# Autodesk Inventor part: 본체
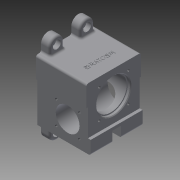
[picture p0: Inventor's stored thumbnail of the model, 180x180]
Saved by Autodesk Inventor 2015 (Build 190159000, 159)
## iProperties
Created: 2024-11
Part Number: 본체
Material: 일반
Document SubType Name: Modeling
Designer: 102-5
Density: 1 g/cm^3
Appearance: 기본값
Author: 102-5
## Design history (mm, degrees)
sketch "스케치1"
  geometry: L1 (-38, 33)-(38, 33); L2 (38, 33)-(38, -52); L3 (38, -52)-(-38, -52); L4 (-38, -52)-(-38, 33); 2 further points
  constraints: 8 end point, 2 parallel, 1 horizontal, 1 midpoint, 1 perpendicular, 1 vertical alignment
  dimensions: "d0" = 76 distance between parallel lines of L2 L4; "d1" = 85 distance between parallel lines of L3 L1; "d2" = 33 distance from line of point (0, 0) L1
extrude "돌출1" new body sketch "스케치1" distance "d3" = 74; taper "d4" = 0 deg
sketch "스케치2"
  geometry: L1 (-33, -38)-(52, -38) reference; L2 (52, -38)-(52, 38) reference; L3 (-4, -38)-(52, -38); L4 (52, -38)-(52, -36); L5 (52, -36)-(-4, -36); L6 (-4, -36)-(-4, -38); 1 further point
  constraints: 8 end point, 2 parallel, 2 point on line, 1 horizontal, 1 perpendicular
  dimensions: "d5" = 2 distance between parallel lines of L5 L1; "d6" = 56 distance between parallel lines of L2 L6
extrude "돌출2" cut sketch "스케치2" stored distance "d7" = 74; taper "d8" = 0 deg
sketch "스케치4"
  geometry: L1 (0, -52)-(-74, -52) reference; L2 (-74, -52)-(-74, 33) reference; L3 (-74, 33)-(0, 33) reference; L4 (0, 33)-(0, -52) reference; L5 (0, 33)-(-74, 33) reference; L6 (-74, -52)-(-74, 4) reference; L7 (-70, 33)-(-74, 33); L8 (-74, 33)-(-74, -33); L9 (-74, -33)-(-70, -33); L10 (-70, -33)-(-70, 33); 1 further point
  constraints: 8 end point, 2 parallel, 2 point on line, 1 horizontal, 1 perpendicular
  dimensions: "d9" = 4 distance between parallel lines of L2 L10; "d10" = 66 distance between parallel lines of L9 L3
extrude "돌출3" cut sketch "스케치4" stored distance "d11" = 4 (= d9); taper "d12" = 0 deg
sketch "스케치5"
  geometry: L1 (33, -38)-(33, 38) reference; L2 (53, 21)-(-72, 21); L3 (43, 31)-(-62, 31); L4 (-62, 11)-(43, 11); A1 r 10 centre (43, 21) between (43, 11) and (43, 31); A2 r 10 centre (-62, 21) between (-62, 31) and (-62, 11); 2 further points
  constraints: 8 end point, 6 point on circle, 4 tangent, 2 centre point, 2 point on line, 1 horizontal, 1 midpoint, 1 parallel
  dimensions: "d15" = 10 radius of A1; "d16" = 21 vertical distance of point (0, 0) A1.centre; "d17" = 105 distance of A2.centre A1.centre; "d18" = 10 distance from line of L1 A1.centre
extrude "돌출4" join sketch "스케치5" distance "d19" = 12; taper "d20" = 0 deg
sketch "스케치6"
  geometry: A1 r 10 centre (-43, 21) between (-43, 31) and (-43, 11) reference; 1 further point
hole "구멍1" sketch "스케치6" at (-43, 21) diameter "d21" = 6.6; stored, may be unused: countersink angle "d25" = 90 deg, drill point angle "d27" = 118 deg; dims "d22" = 6, "d23" = 11, "d24" = 6.6, "d26" = 8
sketch "스케치7"
  geometry: A1 r 10 centre (62, 21) between (62, 11) and (62, 31) reference; 1 further point
hole "구멍2" sketch "스케치7" at (62, 21) diameter "d28" = 6.6; stored, may be unused: countersink angle "d32" = 90 deg, drill point angle "d34" = 118 deg; dims "d29" = 6, "d30" = 11, "d31" = 6.6, "d33" = 8
sketch "스케치8"
  geometry: L1 (0, 0)-(0, 56) reference; L2 (0, 85)-(70, 85) reference; C1 r 16.5 at (42, 28); 1 further point
  constraints: 1 centre point
  dimensions: "d35" = 33 diameter of C1; "d36" = 42 distance from line of C1.centre L1; "d37" = 57 distance from line of C1.centre L2
extrude "돌출5" cut sketch "스케치8" stored distance "d38" = 12; taper "d39" = 0 deg
sketch "스케치9"
  geometry: L1 (42, 28)-(58.5, 28); L2 (42, 28)-(58, 44); 2 further points
  constraints: 4 end point, 1 coincident, 1 horizontal, 1 horizontal alignment, 1 other
  dimensions: "d40" = 45 deg angle of L2 L1; "d42" = 16 horizontal distance of point (58, 44) L1.start
hole "구멍3" sketch "스케치9" at (58, 44) diameter "d43" = 3.242; stored, may be unused: countersink angle "d47" = 90 deg, drill point angle "d49" = 118 deg; dims "d44" = 8, "d45" = 11, "d46" = 6.6, "d48" = 10
sketch "스케치10"
  geometry: L1 (52, -36)-(52, 36) reference; L2 (69.046, -6)-(37, -6); L3 (37, -6)-(37, 6); L4 (37, 6)-(69.046, 6); L5 (69.046, 6)-(69.046, -6); 2 further points
  constraints: 8 end point, 2 parallel, 1 horizontal, 1 horizontal alignment, 1 midpoint, 1 perpendicular
  dimensions: "d53" = 12 distance between parallel lines of L4 L2; "d54" = 15 distance between parallel lines of L1 L3; "d55" = 32.04603 distance between parallel lines of L5 L3
extrude "돌출6" cut sketch "스케치10" stored distance "d56" = 12; taper "d57" = 0 deg
sketch "스케치11"
  geometry: C1 r 23.5 at (33, 38); 1 further point
  constraints: 1 centre point, 1 coincident
  dimensions: "d58" = 47 diameter of C1
extrude "돌출7" cut sketch "스케치11" distance "d59" = 4; taper "d60" = 0 deg
sketch "스케치12"
  geometry: C1 r 23.5 at (0, 0) reference; C2 r 22 at (0, 0)
  constraints: 1 centre point, 1 coincident
  dimensions: "d61" = 44 diameter of C2
extrude "돌출8" cut sketch "스케치12" distance "d62" = 48; taper "d63" = 0 deg
sketch "스케치13"
  geometry: C1 r 22 at (0, 0) reference; C2 r 17.5 at (0, 0)
  constraints: 1 centre point, 1 coincident
  dimensions: "d64" = 35 diameter of C2
extrude "돌출9" cut sketch "스케치13" distance "d65" = 11; taper "d66" = 0 deg
sketch "스케치14"
  geometry: C1 r 17.5 at (0, 0) reference; C2 r 15 at (0, 0)
  constraints: 1 centre point, 1 coincident
  dimensions: "d67" = 30 diameter of C2
extrude "돌출10" cut sketch "스케치14" distance "d68" = 3; taper "d69" = 0 deg
fillet "모깎기1" dims "d70" = 3
fillet "모깎기2" dims "d71" = 0.6
chamfer "모따기1" distance "d72" = 1; stored, may be unused: second distance "d73" = 2, angle "d74" = 45 deg
fillet "모깎기3" dims "d75" = 3
chamfer "모따기2" distance "d76" = 1; stored, may be unused: second distance "d77" = 2, angle "d78" = 45 deg
sketch "스케치15"
  geometry: L1 (33, 38)-(12.847, 58.153); L2 (33, 38)-(4.5, 38); C1 r 24.5 at (33, 38) reference; A1 r 28.5 centre (33, 38) between (12.847, 58.153) and (4.5, 38)
  constraints: 4 end point, 2 point on circle, 1 centre point, 1 coincident, 1 horizontal
  dimensions: "d79" = 57 diameter of A1; "d81" = 45 deg angle of L1 L2
hole "구멍4" sketch "스케치15" at (12.847, 58.153) diameter "d82" = 3.242; stored, may be unused: countersink angle "d86" = 90 deg, drill point angle "d88" = 118 deg; dims "d83" = 8, "d84" = 11, "d85" = 6.6, "d87" = 10
sketch "스케치16"
  geometry: L1 (0, 0)-(0, 12) reference; L2 (74, 12)-(74, 0) reference; 4 further points
  constraints: 2 horizontal alignment, 1 midpoint
  dimensions: "d92" = 40 distance of point (12, 6) point (52, 6); "d93" = 12 distance from line of point (12, 6) L1
hole "구멍5" sketch "스케치16" at (12, 6), (52, 6) diameter "d94" = 3.242; stored, may be unused: countersink angle "d98" = 90 deg, drill point angle "d100" = 118 deg; dims "d95" = 8, "d96" = 11, "d97" = 6.6, "d99" = 10
fillet "모깎기4" dims "d101" = 3
fillet "모깎기5" dims "d102" = 3
fillet "모깎기6" dims "d103" = 3
sketch "스케치17"
  geometry: L1 (0, 0)-(0, 16) reference; L2 (70, -27)-(70, 43) reference; 3 further points
  constraints: 1 horizontal alignment, 1 midpoint, 1 other
  dimensions: "d105" = 20 distance from line of L2 point (50, 8)
feature "엠보싱1" sketch "스케치17" dims "d106" = 0.5, "d107" = 0
chamfer "모따기3" distance "d108" = 1; stored, may be unused: second distance "d109" = 2, angle "d110" = 45 deg
fillet "모깎기8" dims "d111" = 3
node "솔리드1"
mirror "대칭1"
mirror "대칭2"
pattern_circular "원형 패턴1" dims angle "d51" = 360 deg
mirror "대칭3"
pattern_circular "원형 패턴2" dims angle "d90" = 360 deg
node "절단 모서리 투영1"
other parameters: "d80" = 45 deg
